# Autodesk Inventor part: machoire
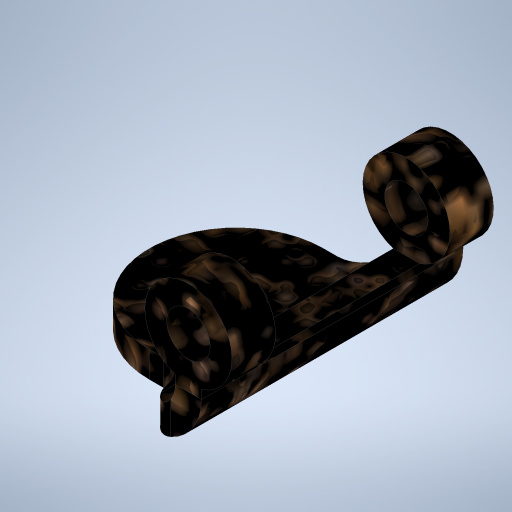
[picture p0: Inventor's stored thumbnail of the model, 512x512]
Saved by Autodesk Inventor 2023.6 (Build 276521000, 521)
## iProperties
Created: 2026-01
Part Number: machoire
Material: Générique
Document SubType Name: Sheet Metal
Designer: mel
Density: 1 g/cm^3
Sheet Metal Rule: Par défaut_mm
Appearance: Terre battue - Brun foncé
Author: mel
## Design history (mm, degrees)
node "Face1"
  sketch "Esquisse1"
    geometry: L1 (6.707, 43.633)-(1.707, 43.633); L2 (1.707, 43.633)-(1.707, 13.633); L3 (1.707, 13.633)-(6.707, 13.633); C1 r 2.5 at (6.707, 28.633); A1 r 15 centre (6.707, 28.633) between (6.707, 13.633) and (6.707, 43.633); 2 further points
    constraints: 6 end point, 2 centre point, 2 point on circle
node "Bord tombé1"
sketch "Esquisse3"
  geometry: L1 (0, 0)-(3, 0) reference; C1 r 2.5 at (1.5, 4.77); A1 r 5 centre (1.5, 4.77) between (0, 0) and (3, 0); 1 further point
  constraints: 2 centre point, 2 point on circle, 1 coincident
  dimensions: "d11" = 5 diameter of C1; "d12" = 10 diameter of A1
extrude "Extrusion1" join sketch "Esquisse3" stored distance "d13" = 10; taper "d14" = 0 deg
sketch "Esquisse4"
  geometry: L1 (0, 10.77)-(30, 10.77) reference; L2 (0, 1)-(30, 1) reference; L3 (5, 10.77)-(25, 10.77); L4 (25, 10.77)-(25, 1); L5 (25, 1)-(5, 1); L6 (5, 1)-(5, 10.77); L7 (0, 10.77)-(0, 1) reference; L8 (30, 10.77)-(30, 1) reference; 3 further points
  constraints: 8 end point, 2 parallel, 2 point on line, 1 horizontal, 1 perpendicular
  dimensions: "d15" = 5 distance between parallel lines of L7 L6; "d16" = 5 distance between parallel lines of L8 L4 (= d15)
extrude "Extrusion2" cut sketch "Esquisse4" extent not by distance; stored distance "d17" = 0; taper "d18" = 0 deg
sketch "Esquisse5"
  geometry: L1 (7.793, -18.633)-(-2.207, -18.633) reference; L2 (-2.207, -18.633)-(-22.694, -18.633); L3 (-22.694, -18.633)-(-22.694, -11.696); L4 (-22.694, -11.696)-(-2.207, -11.696); L5 (-2.207, -11.696)-(-2.207, -18.633); L6 (-2.207, -38.633)-(7.793, -38.633) reference; L7 (-2.207, -38.633)-(-22.694, -38.633); L8 (-22.694, -38.633)-(-22.694, -45.743); L9 (-22.694, -45.743)-(-2.207, -45.743); L10 (-2.207, -45.743)-(-2.207, -38.633); 5 further points
  constraints: 16 end point, 4 parallel, 2 horizontal, 2 perpendicular, 1 point on line
extrude "Extrusion3" cut sketch "Esquisse5" extent not by distance; stored distance "d19" = 0; taper "d20" = 0 deg
fillet "Congé1" dims "d21" = 3
sketch "Esquisse6"
  geometry: L1 (-16.453, -18.633)-(-5.123, -18.633) reference; L2 (-6.707, -18.633)-(-6.707, -10.497); L3 (-6.707, -10.497)-(-22.345, -19.986); L4 (-22.345, -19.986)-(-23.087, -37.851); L5 (-23.087, -37.851)-(-9.675, -45.697); L6 (-9.675, -45.697)-(-6.707, -38.633); L7 (-5.123, -38.633)-(-16.453, -38.633) reference; C1 r 2.5 at (-6.707, -28.633) reference; A1 r 10 centre (-6.707, -28.633) between (-6.707, -18.633) and (-6.707, -38.633); 1 further point
  constraints: 10 end point, 2 point on circle, 2 point on line, 1 centre point, 1 coincident, 1 tangent, 1 vertical
extrude "Extrusion4" cut sketch "Esquisse6" extent not by distance; stored distance "d22" = 0; taper "d23" = 0 deg
node "Solide1"
feature "Plaque1" dims "d0" = 3 (= Epaisseur)
sketch "Esquisse2"
  geometry: L1 through (0, 15) direction (-2.27e-32, -1); L2 through (0.5, 0) direction (1, -2.27e-32); L3 (1, 0)-(1, 30); L4 (1, 30)-(0, 30)
  constraints: 6 end point, 1 horizontal, 1 perpendicular, 1 vertical
feature "Plaque2" dims "d0" = 3 (= Epaisseur), "d1" = 3 (= LargeurGrugeage), "d2" = 1.5 (= ProfondeurGrugeage), "d3" = 6 (= RestesMinimum), "d4" = 3 (= Rayondetransition), "d5" = 7, "d6" = 90 deg, "d7" = 3 (= RayonPli), "d8" = 12 (= TailleGrugeage), "d9" = 3 (= TailleJeu), "d10" = 3 (= TailleRayonJacobi), "SeamGap" = 0.01
feature "Pli1" dims "d0" = 3 (= Epaisseur), "d1" = 3 (= LargeurGrugeage), "d2" = 1.5 (= ProfondeurGrugeage), "d3" = 6 (= RestesMinimum), "d4" = 3 (= Rayondetransition), "d5" = 7, "d6" = 90 deg, "d7" = 3 (= RayonPli), "SeamGap" = 0.01
feature "Coin1" dims "d5" = 7, "d6" = 90 deg, "d8" = 12 (= TailleGrugeage), "d9" = 3 (= TailleJeu), "d10" = 3 (= TailleRayonJacobi)
other parameters: "Epaisseur" = 3 (derived), "RayonPli" = 3 (= Epaisseur), "LargeurGrugeage" = 3 (= Epaisseur), "ProfondeurGrugeage" = 1.5 (= 0.5 x Epaisseur), "TailleGrugeage" = 12 (= 4 x Epaisseur), "RestesMinimum" = 6 (= 2 x Epaisseur), "Rayondetransition" = 3 (= RayonPli), "TailleRayonJacobi" = 3 (= RayonPli), "TailleJeu" = 3 (= Epaisseur)
